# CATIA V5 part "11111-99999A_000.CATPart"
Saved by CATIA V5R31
Part number: 11111-99999A_000
Revision:  001
Nomenclature: TRIM,FRONT PILLAR,R
Source: Unknown
Property "部品番号(A社)": "11111-99999"
Property "部品名称 (A社)": "TRIM,FRONT PILLAR,R"
Property "Version (A社)": "001"
Property "材質(A社)": "PP-JAMA9"
Property "板厚": "2"
Bounding box of the stored display mesh (mm): x -596.348 to -514.362, y 913.531 to 1307.189, z 734.649 to 1101.166
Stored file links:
  \\solize.local\damia\dept\DDE_Design\10_order\2305701_JAMA_変換検証STEP3_お手本モデル作成\Fini\07_スズキ\CATIAV5\11111-99999A_000.CATPart
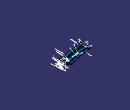
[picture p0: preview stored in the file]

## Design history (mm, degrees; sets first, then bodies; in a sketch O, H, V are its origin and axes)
TTRSSet1
f4a2d38f3ddc11d3a929006094b99c4b_11 "CATTPSSet"
Set1
  Point1 "CARTESIAN_POINT #16800": stored without definition
  Point2 "CARTESIAN_POINT #16801": stored without definition
  Point3 "CARTESIAN_POINT #16802": stored without definition
  Point4 "CARTESIAN_POINT #16803": stored without definition
  Circle1 "CIRCLE #5681": stored without definition
  DatumCurve1 "B_SPLINE_CURVE_WITH_KNOTS #4931"
  DatumCurve2 "B_SPLINE_CURVE_WITH_KNOTS #4932"
  DatumCurve3 "B_SPLINE_CURVE_WITH_KNOTS #4933"
  DatumCurve4 "B_SPLINE_CURVE_WITH_KNOTS #4934"
  DatumCurve5 "B_SPLINE_CURVE_WITH_KNOTS #4935"
  DatumCurve6 "B_SPLINE_CURVE_WITH_KNOTS #4936"
  DatumCurve7 "B_SPLINE_CURVE_WITH_KNOTS #4937"
  DatumCurve8 "B_SPLINE_CURVE_WITH_KNOTS #4938"
  DatumCurve9 "B_SPLINE_CURVE_WITH_KNOTS #4939"
  DatumCurve10 "B_SPLINE_CURVE_WITH_KNOTS #4940"
  DatumCurve11 "B_SPLINE_CURVE_WITH_KNOTS #4941"
  DatumCurve12 "B_SPLINE_CURVE_WITH_KNOTS #4942"
  DatumCurve13 "B_SPLINE_CURVE_WITH_KNOTS #4943"
  DatumCurve14 "B_SPLINE_CURVE_WITH_KNOTS #4944"
  DatumSurface1 to DatumSurface4
  AxisSystem1: origin (0, 0, 0), X (0.7071, 0.183, 0.683), Y (-0.7071, 0.183, 0.683), Z (0, -0.9659, 0.2588)
Body1 "Partbody" (main body)
Body2 "MANIFOLD_SOLID_BREP #513"
  Solid1: solid without history
Body3 "MANIFOLD_SOLID_BREP #514"
  Solid2: solid without history
Body4 "MANIFOLD_SOLID_BREP #515"
  Solid3: solid without history
Body5 "MANIFOLD_SOLID_BREP #516"
  Solid4: solid without history
Body6 "MANIFOLD_SOLID_BREP #517"
  Solid5: solid without history
Body7 "MANIFOLD_SOLID_BREP #518"
  Solid6: solid without history
Body8 "MANIFOLD_SOLID_BREP #519"
  Solid7: solid without history
Body9 "MANIFOLD_SOLID_BREP #520"
  Solid8: solid without history
Body10 "MANIFOLD_SOLID_BREP #521"
  Solid9: solid without history
Body11 "MANIFOLD_SOLID_BREP #522"
  Solid10: solid without history
Body12 "MANIFOLD_SOLID_BREP #523"
  Solid11: solid without history
Body13 "MANIFOLD_SOLID_BREP #524"
  Solid12: solid without history
Body14 "MANIFOLD_SOLID_BREP #525"
  Solid13: solid without history
Body15 "MANIFOLD_SOLID_BREP #512"
  Solid14: solid without history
